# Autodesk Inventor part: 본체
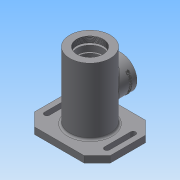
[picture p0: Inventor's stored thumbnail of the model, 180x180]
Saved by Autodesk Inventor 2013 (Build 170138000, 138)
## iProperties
Created: 2017-10
Part Number: 본체
Material: 일반
Document SubType Name: Modeling
Designer: Administrator
Density: 1 g/cm^3
Author: Administrator
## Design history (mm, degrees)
sketch "스케치1"
  geometry: L1 (-38, -47)-(38, -47); L2 (58, -27)-(58, 27); L3 (38, 47)-(-38, 47); L4 (-58, 27)-(-58, -27); L5 (-58, -47)-(58, 47); L6 (58, -47)-(-58, 47); L7 (-50, 20)-(-50, -20); L8 (-42, 20)-(-42, -20); L9 (42, 20)-(42, -20); L10 (50, 20)-(50, -20); L11 (-38, 47)-(-58, 27); L12 (-58, -27)-(-38, -47); L13 (38, -47)-(58, -27); L14 (58, 27)-(38, 47); A1 r 4 centre (46, 20) between (50, 20) and (42, 20); A2 r 4 centre (46, -20) between (42, -20) and (50, -20); A3 r 4 centre (-46, -20) between (-50, -20) and (-42, -20); A4 r 4 centre (-46, 20) between (-42, 20) and (-50, 20); 3 further points
  constraints: 28 end point, 8 point on circle, 8 point on line, 7 tangent, 4 centre point, 3 equal radius, 3 midpoint, 3 parallel, 2 horizontal alignment, 2 vertical alignment, 1 coincident, 1 horizontal, 1 perpendicular
  dimensions: "d0" = 116 distance of L6.end L5.end; "d1" = 94 distance of L5.end L6.start; "d2" = 20 vertical distance of A2.centre point (0, 0); "d3" = 40 distance of A1.centre A2.centre; "d4" = 46 horizontal distance of A3.centre point (0, 0); "d5" = 92 distance of A2.centre A3.centre; "d6" = 8 diameter of A1; "d7" = 20 distance of L3.end L6.end; "d8" = 20 distance of L4.start L6.end (= d7); "d9" = 20 distance of L4.end L5.start (= d7); "d10" = 20 distance of L1.start L5.start (= d9); "d11" = 20 distance of L1.end L6.start (= d7); "d12" = 20 distance of L2.start L6.start (= d11); "d13" = 20 distance of L2.end L5.end (= d7); "d14" = 20 distance of L3.start L5.end (= d13)
extrude "돌출1" new body sketch "스케치1" distance "d15" = 10; taper "d16" = 0 deg
sketch "스케치2"
  geometry: C1 r 31 at (0, 0); 1 further point
  constraints: 1 centre point, 1 coincident
  dimensions: "d17" = 62 diameter of C1
extrude "돌출2" join sketch "스케치2" distance "d18" = 102; taper "d19" = 0 deg
sketch "스케치3"
  geometry: C1 r 35 at (0, 0); 1 further point
  constraints: 1 centre point, 1 coincident
  dimensions: "d20" = 70 diameter of C1
extrude "돌출3" join sketch "스케치3" distance "d21" = 3; taper "d22" = 0 deg
sketch "스케치4"
  geometry: L1 (-35, -3)-(35, -3) reference; L2 (-31, 10)-(-31, 112) reference; L3 (31, 112)-(-31, 112) reference; L4 (31, 10)-(31, 112) reference; L5 (0, 112)-(0, -3); L6 (22, -3)-(16, 11); L7 (16, 11)-(12.5, 11); L8 (12.5, 11)-(12.5, 18.3); L9 (12.5, 18.3)-(10, 18.3); L10 (10, 18.3)-(10, 21); L11 (10, 21)-(16.5, 21); L12 (16.5, 21)-(16.5, 26); L13 (16.5, 26)-(17.5, 26); L14 (17.5, 26)-(17.5, 37); L15 (17.5, 37)-(26, 37); L16 (26, 37)-(26, 75); L17 (26, 75)-(17.5, 75); L18 (17.5, 75)-(17.5, 84.25); L19 (17.5, 84.25)-(18.5, 84.25); L20 (18.5, 84.25)-(18.5, 86); L21 (18.5, 86)-(17.5, 86); L22 (17.5, 86)-(17.5, 91); L23 (17.5, 91)-(20, 91); L24 (20, 91)-(20, 100); L25 (20, 100)-(24, 100); L26 (24, 100)-(24, 103); L27 (24, 103)-(0, 103); L28 (22, -3)-(0, -3); 1 further point
  constraints: 48 end point, 21 perpendicular, 2 midpoint, 2 point on line, 1 parallel
  dimensions: "d26" = 14 distance between parallel lines of L7 L28; "d27" = 7.3 distance between parallel lines of L9 L7; "d28" = 2.7 distance between parallel lines of L11 L9; "d32" = 22 distance of L5.end L6.start; "d33" = 32 diameter of L6.end L5; "d34" = 25 diameter of L8 L5; "d35" = 20 diameter of L10 L5; "d36" = 33 diameter of L12 L5; "d37" = 5 distance of L11.end L12.end; "d38" = 11 distance of L13.end L14.end; "d39" = 35 diameter of L14 L5; "d40" = 52 diameter of L16 L5; "d41" = 38 distance of L15.end L16.end; "d43" = 35 diameter of L18 L5; "d44" = 11 distance between parallel lines of L21 L17; "d45" = 1.75 distance of L19.end L20.end; "d46" = 37 diameter of L20 L5; "d47" = 35 diameter of L22 L5; "d48" = 12 distance between parallel lines of L25 L3; "d49" = 3 distance between parallel lines of L25 L27; "d50" = 48 diameter of L26 L5; "d51" = 40 diameter of L24 L5; "d52" = 21 distance between parallel lines of L23 L3
revolve "회전1" sketch "스케치4" stored, may be unused: angle "d53" = 90 deg
sketch "스케치5"
  geometry: C1 r 31 at (0, 0) reference
hole "구멍1" sketch "스케치5" at (0, 0) diameter "d54" = 40.376; stored, may be unused: countersink angle "d58" = 90 deg, drill point angle "d60" = 0 deg; dims "d55" = 6, "d56" = 48, "d57" = 3, "d59" = 9
sketch "스케치6"
  geometry: L1 (76, 0)-(0, 0) reference; L2 (7, -112)-(69, -112) reference; C1 r 25 at (38, -56); 2 further points
  constraints: 1 centre point, 1 midpoint, 1 vertical alignment
  dimensions: "d61" = 50 diameter of C1; "d62" = 56 distance from line of C1.centre L2
extrude "돌출4" join sketch "스케치6" stored distance "d63" = 3; taper "d64" = 0 deg
sketch "스케치7"
  geometry: C1 r 25 at (0, 0) reference; 1 further point
hole "구멍2" sketch "스케치7" at (0, 0) diameter "d65" = 32; stored, may be unused: countersink angle "d69" = 90 deg, drill point angle "d71" = 0 deg; dims "d66" = 6, "d67" = 48, "d68" = 3, "d70" = 9
sketch "스케치8"
  geometry: C1 r 16 at (0, 0) reference; C2 r 25 at (0, 0) reference; A1 r 20.5 centre (0, 0) between (-20.5, 0) and (20.5, 0); 1 further point
  constraints: 2 horizontal alignment, 2 point on circle, 1 centre point, 1 coincident
  dimensions: "d72" = 41 diameter of A1
hole "구멍3" sketch "스케치8" at (-20.5, 0), (20.5, 0) diameter "d73" = 2.459; stored, may be unused: countersink angle "d77" = 90 deg, drill point angle "d79" = 118 deg; dims "d74" = 6, "d75" = 48, "d76" = 3, "d78" = 8
node "작업 평면1"
sketch "스케치9"
  geometry: L1 (31, 112)-(-31, 112) reference; L2 (47, 81)-(47, 31) reference; 2 further points
  constraints: 1 other
  dimensions: "d81" = 56 distance from line of point (37, 56) L1; "d82" = 10 distance from line of point (37, 56) L2
feature "엠보싱1" sketch "스케치9" dims "d0" = 116, "d1" = 94, "d7" = 20, "d8" = 20 (= d7), "d9" = 20 (= d7), "d10" = 20 (= d9), "d11" = 20 (= d7), "d12" = 20 (= d11), "d13" = 20 (= d7), "d14" = 20 (= d13), "d83" = 0.5, "d84" = 0
chamfer "모따기1" distance "d85" = 1; stored, may be unused: second distance "d86" = 2, angle "d87" = 45 deg
chamfer "모따기2" distance "d88" = 0.7; stored, may be unused: second distance "d89" = 2, angle "d90" = 30 deg
fillet "모깎기1" dims "d91" = 0.3, "d92" = 3
node "솔리드1"
other parameters: "d80" = 25.5
